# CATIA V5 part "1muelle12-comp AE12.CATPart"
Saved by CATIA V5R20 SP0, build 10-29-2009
Part number: 1muelle12-comp AE12
Revision: ANY
Definition: UNKNOWN
Nomenclature: 1muelle12-comp AE12
Source: Unknown
Bounding box of the stored display mesh (mm): x -7.75 to 7.75, y -7.75 to 7.75, z -0.001 to 9.449
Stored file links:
  C:\Users\Utente\Desktop\IO LAVORO\3D X SITO CF\CUMSA\3D files BA\BA 122024\1muelle12-comp AE12.CATPart
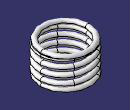
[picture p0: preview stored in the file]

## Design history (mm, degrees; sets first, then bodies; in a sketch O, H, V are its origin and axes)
Set1 "FacciaKO#NONE#1362"
  DatumSurface1 "Sup1362_1"
  DatumCurve1 "Crv1362_1"
Set2 "FacciaKO#NONE#1385"
  DatumSurface2 "Sup1385_1"
  DatumCurve2 "Crv1385_1"
Body1 "Cortar-Extruir1" (main body)
  Solid1: solid without history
